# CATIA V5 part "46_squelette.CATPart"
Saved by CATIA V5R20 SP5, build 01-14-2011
Part number: 46_squelette
Publications: "Plan yz", "Plan.1"
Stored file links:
  C:\Documents and Settings\anizard\Bureau\13\46_squelette.CATPart
  C:\Documents and Settings\anizard\Bureau\13\anizard.CATProduct
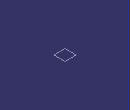
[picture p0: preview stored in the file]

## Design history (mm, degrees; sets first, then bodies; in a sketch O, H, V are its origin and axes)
Parameters
  epaisseur = 8 mm
Set1
  Plane1: linked copy from another document
Body1 (main body)
  Plane2: type Offset, RefPlane Plane1, Offset 8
